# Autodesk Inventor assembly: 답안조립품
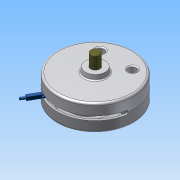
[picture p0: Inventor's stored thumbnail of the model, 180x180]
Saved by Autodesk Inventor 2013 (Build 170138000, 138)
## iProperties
Created: 2015-06
Part Number: 답안조립품
Document SubType Name: Assembly
Designer: Administrator
Author: Administrator
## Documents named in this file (10)
- C:\Documents and Settings\Administrator\바탕 화면\450631V1015\답안조립품.iam
- C:\Documents and Settings\Administrator\바탕 화면\450631V1015\1-본체.ipt
- C:\Documents and Settings\Administrator\바탕 화면\450631V1015\베어링62_22.ipt
- C:\Documents and Settings\Administrator\바탕 화면\450631V1015\덮개.ipt
- C:\Documents and Settings\Administrator\바탕 화면\450631V1015\멈춤링.ipt
- C:\Documents and Settings\Administrator\바탕 화면\450631V1015\축.ipt
- C:\Documents and Settings\Administrator\바탕 화면\450631V1015\슬라이더.ipt
- C:\Documents and Settings\Administrator\바탕 화면\450631V1015\슬라이더2.ipt
- C:\Documents and Settings\Administrator\바탕 화면\450631V1015\평행핀.ipt
- C:\Documents and Settings\Administrator\바탕 화면\450631V1015\M10x35.ipt
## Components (8 placed, 5 different names)
1. 1-본체:1 — 각도:1
2. KS B 2023 62/22 - 22 x 50 x 14:1
3. KS B 2023 62/22 - 22 x 50 x 14:2
4. KS B 1336 22 x 1.2:1
5. KS B 1336 22 x 1.2:2
6. KS B 1320 B B 5 x  20:1
7. KS B 1003 - 미터 M 10 x 35:1
8. KS B 1003 - 미터 M 10 x 35:2
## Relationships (1: Angle 1)
- 각도:1 [Angle]: 1-본체:1
